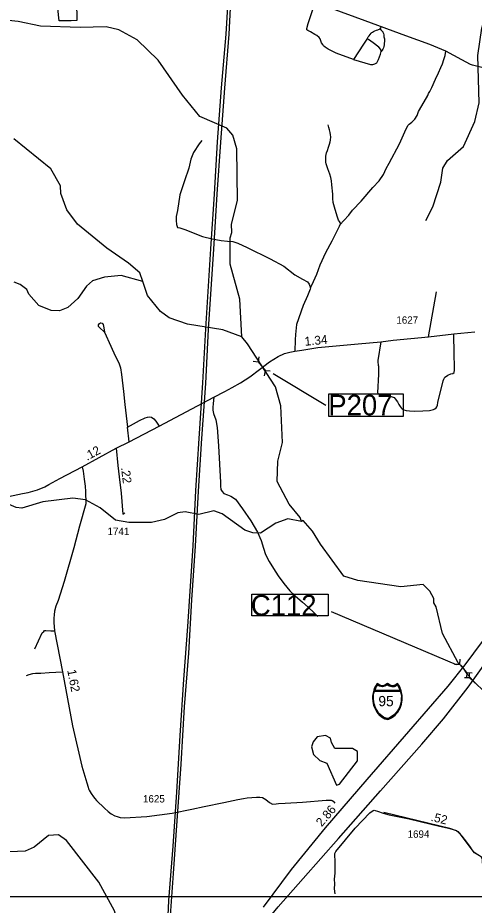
# Model space of a CAD drawing. Extents: x 2290615 to 2522933, y 819489 to 1012715.
# Drawn here: x 2389068 to 2396841, y 958270 to 973391 of the extents above; entities that cross this region are included whole.
import ezdxf

# ---------------------------------------------------------------- set-up
doc = ezdxf.new("R2010")
doc.units = 0
for name, color, linetype in [('Exist Hydrographic Creek Single Shore', 7, 'Continuous'), ('Exist Hydrographic Misc Water Feature', 7, 'Continuous'), ('Exist Hydrographic Pond Under 1500 Sq Ft', 7, 'Continuous'), ('Exist Road Non-System Type 51', 7, 'Continuous'), ('Exist Road Primary Interstate Divided Center Attributed', 7, 'Continuous'), ('Exist Road Primary Interstate Mileage Hundredths English Label', 7, 'Continuous'), ('Exist Road Primary Interstate Shield CELL', 7, 'Continuous'), ('Exist Road Primary Interstate Shield Number Label', 7, 'Continuous'), ('Exist Road Primary Interstate Structure Culvert CELL', 7, 'Continuous'), ('Exist Road Primary Interstate Structure Culvert Number Label', 7, 'Continuous'), ('Exist Road Secondary Mileage Hundredths English Label', 7, 'Continuous'), ('Exist Road Secondary Structure Pipe CELL', 7, 'Continuous'), ('Exist Road Secondary Structure Pipe Number Label', 7, 'Continuous'), ('Exist Road Secondary Type 51 Attributed', 7, 'Continuous'), ('Exist Road Secondary Type 51 Number Label', 7, 'Continuous'), ('Exist Utilities Electrical Transmission Line', 7, 'Continuous'), ('Map Preparation Inset Cut Line', 7, 'Continuous')]:
    doc.layers.add(name, color=color, linetype=linetype)

msp = doc.modelspace()

# ---------------------------------------------------------------- linework, layer by layer
at = {"layer": 'Exist Hydrographic Creek Single Shore'}
for points in [[(2396016, 969935), (2396138, 970170), (2396274, 970589), (2396304, 970830), (2396386, 970958), (2396658, 971196), (2396852, 971621), (2396923, 971939), (2396904, 972749), (2396973, 973215), (2397021, 973381), (2397542, 974289), (2397869, 974736), (2398059, 974894), (2398348, 975074), (2398516, 975142), (2398940, 975254), (2399468, 975422), (2399702, 975418), (2400062, 975289), (2400494, 975362)], [(2391197, 968897), (2390829, 969000), (2390546, 968972), (2390339, 968911), (2390240, 968818), (2390093, 968609), (2389920, 968457), (2389779, 968395), (2389637, 968403), (2389428, 968489), (2389259, 968679), (2389224, 968763), (2389107, 968844), (2389006, 968886)], [(2392885, 967952), (2392558, 968073), (2391957, 968173), (2391647, 968278), (2391496, 968384), (2391275, 968657), (2391197, 968897)], [(2393901, 964809), (2393875, 964874), (2393689, 965106), (2393484, 965488), (2393496, 965837), (2393575, 966155), (2393550, 966778), (2393454, 967102), (2392978, 967837), (2392885, 967952)], [(2397039, 961885), (2396818, 962099), (2396734, 962195), (2396647, 962324), (2396567, 962399), (2396301, 962899), (2396195, 963357), (2396152, 963421), (2396151, 963497), (2396083, 963622), (2395973, 963735), (2395591, 963697), (2394856, 963804), (2394622, 963877), (2394223, 964422), (2394086, 964646), (2393926, 964827), (2393901, 964809)], [(2390741, 958077), (2390738, 958090), (2390714, 958175), (2390450, 958663), (2389898, 959372), (2389764, 959472), (2389589, 959461), (2389350, 959258), (2389193, 959189), (2388935, 959178), (2388609, 959247), (2388315, 959386), (2387641, 959959), (2387514, 960135), (2386992, 961150), (2386714, 961366), (2386572, 961412)]]:
    msp.add_lwpolyline(points, dxfattribs=at)
at = {"layer": 'Exist Hydrographic Misc Water Feature'}
for points in [[(2392885, 967952), (2392851, 968594), (2392685, 969191), (2392687, 969641), (2392711, 969734), (2392709, 969875), (2392812, 970276), (2392800, 971159), (2392731, 971393), (2392629, 971507), (2392168, 971711), (2391872, 972073), (2391456, 972666), (2391101, 973013), (2390791, 973184), (2390573, 973237), (2390132, 973226), (2389457, 973247), (2389072, 973327), (2388805, 973358), (2388645, 973513), (2388377, 973626), (2388325, 973769)], [(2391197, 968897), (2391145, 969046), (2390951, 969212), (2390582, 969466), (2390085, 969875), (2389906, 970121), (2389803, 970396), (2389793, 970530), (2389631, 970819), (2388999, 971328)], [(2393901, 964809), (2393667, 964855), (2393460, 964778), (2393204, 964607), (2393070, 964614), (2392937, 964661), (2392549, 964941), (2392407, 964988), (2392150, 964928), (2391916, 964974), (2391791, 964956), (2391567, 964845), (2391343, 964793), (2390960, 964793), (2390735, 964833), (2390473, 965039), (2390222, 965177), (2390005, 965207), (2389497, 965144), (2389140, 965037), (2389040, 965046), (2388923, 965100), (2388745, 965323), (2388692, 965573)]]:
    msp.add_lwpolyline(points, dxfattribs=at)
at = {"layer": 'Exist Hydrographic Pond Under 1500 Sq Ft'}
msp.add_lwpolyline([(2394544, 960335), (2394855, 960732), (2394853, 960889), (2394769, 960938), (2394469, 960942), (2394409, 961042), (2394391, 961116), (2394308, 961165), (2394166, 961137), (2394101, 961055), (2394069, 960968), (2394103, 960839), (2394213, 960738), (2394331, 960690), (2394494, 960316), (2394544, 960335)], dxfattribs=at)
at = {"layer": 'Exist Road Non-System Type 51'}
for p, q in [((2396062, 967957), (2396198, 968719)), ((2390967, 966166), (2390939, 966417)), ((2390967, 966166), (2390939, 966417))]:
    msp.add_line(p, q, dxfattribs=at)
for points in [[(2390053, 974302), (2390055, 974217), (2390057, 974000), (2390059, 973821), (2390070, 973583), (2390074, 973429), (2390074, 973346), (2389976, 973340), (2389804, 973338), (2389775, 973340), (2389765, 973390), (2389755, 973496), (2389748, 973641), (2389734, 973863), (2389724, 974025), (2389724, 974118), (2389726, 974168)], [(2394786, 972682), (2394490, 972790), (2394352, 972856), (2394302, 972887), (2394277, 972912), (2394261, 972934), (2394240, 972964), (2394228, 972997), (2394215, 973032), (2394198, 973057), (2394161, 973087), (2394124, 973108), (2394055, 973149), (2394007, 973171), (2393991, 973185), (2393993, 973210), (2394013, 973292), (2394056, 973430), (2394133, 973646)], [(2395017, 973034), (2395027, 973056), (2395035, 973068), (2395049, 973084), (2395069, 973107), (2395087, 973128), (2395100, 973139), (2395111, 973147), (2395126, 973157), (2395149, 973167), (2395175, 973178), (2395199, 973187), (2395213, 973191), (2395227, 973197), (2395239, 973200)], [(2395239, 973200), (2395250, 973218), (2395259, 973236)], [(2395239, 973200), (2395253, 973184), (2395269, 973166), (2395280, 973156), (2395285, 973149), (2395287, 973143), (2395290, 973133), (2395295, 973121), (2395299, 973101), (2395302, 973082), (2395304, 973068), (2395309, 973049), (2395312, 973032), (2395311, 973008), (2395311, 972984), (2395308, 972959), (2395305, 972929), (2395302, 972903), (2395296, 972881), (2395286, 972857), (2395276, 972837), (2395258, 972818)], [(2395017, 973034), (2395014, 973028), (2395001, 973011), (2394958, 972943), (2394786, 972682)], [(2395258, 972818), (2395248, 972849), (2395214, 972891), (2395118, 972965), (2395041, 973019), (2395029, 973028), (2395017, 973034)], [(2394558, 969866), (2394620, 969934), (2394706, 970026), (2394770, 970111), (2394914, 970266), (2395117, 970498), (2395223, 970612), (2395294, 970723), (2395344, 970823), (2395394, 970915), (2395566, 971243), (2395684, 971498), (2395718, 971558), (2395735, 971575), (2395776, 971611), (2395828, 971665), (2395868, 971728), (2395893, 971792), (2395947, 971893), (2396050, 972064), (2396064, 972101), (2396083, 972133), (2396119, 972204), (2396183, 972344), (2396231, 972454), (2396273, 972542), (2396298, 972605), (2396323, 972680), (2396344, 972747), (2396359, 972819)], [(2394786, 972682), (2395072, 972597), (2395113, 972597), (2395150, 972608), (2395185, 972624), (2395213, 972678), (2395244, 972770), (2395258, 972818)], [(2394558, 969866), (2394561, 969877), (2394561, 969887), (2394556, 969902), (2394547, 969919), (2394532, 969945), (2394505, 970008), (2394460, 970163), (2394441, 970245), (2394431, 970310), (2394431, 970387), (2394418, 970542), (2394409, 970612), (2394399, 970670), (2394382, 970728), (2394349, 970816), (2394330, 970866), (2394321, 970903), (2394316, 970929), (2394313, 970983), (2394316, 971034), (2394327, 971090), (2394341, 971132), (2394357, 971185), (2394376, 971236), (2394389, 971276), (2394393, 971303), (2394399, 971361), (2394394, 971394), (2394389, 971438), (2394378, 971481), (2394367, 971519), (2394356, 971567)], [(2392202, 971302), (2392157, 971240), (2392062, 971095), (2392016, 970981), (2391980, 970828), (2391908, 970615), (2391830, 970374), (2391788, 970109), (2391767, 970005), (2391766, 969937), (2391773, 969869), (2391788, 969820), (2391827, 969812), (2391915, 969783), (2392214, 969662), (2392376, 969622), (2392531, 969595), (2392638, 969587), (2392731, 969577), (2392813, 969551), (2392974, 969479), (2393368, 969286), (2393600, 969159), (2393785, 969010), (2393917, 968937), (2394000, 968889), (2394031, 968852), (2394050, 968791)], [(2394050, 968791), (2394106, 968895), (2394160, 969021), (2394220, 969182), (2394316, 969389), (2394419, 969589), (2394496, 969739), (2394548, 969840), (2394558, 969866)], [(2394050, 968791), (2394047, 968769), (2394004, 968651), (2393930, 968489), (2393813, 968162), (2393796, 967996), (2393792, 967906), (2393786, 967713)], [(2390543, 968032), (2390458, 968111), (2390445, 968133), (2390443, 968157), (2390459, 968179), (2390474, 968191), (2390480, 968191), (2390507, 968186), (2390523, 968162), (2390534, 968106), (2390543, 968032)], [(2390543, 968032), (2390458, 968111), (2390445, 968133), (2390443, 968157), (2390459, 968179), (2390474, 968191), (2390480, 968191), (2390507, 968186), (2390523, 968162), (2390534, 968106), (2390543, 968032)], [(2390543, 968032), (2390655, 967798), (2390726, 967630), (2390772, 967548), (2390795, 967493), (2390815, 967425), (2390835, 967310), (2390868, 967023), (2390890, 966804), (2390939, 966417)], [(2395249, 967871), (2395201, 967550), (2395200, 967516), (2395204, 967482), (2395206, 967474), (2395210, 967453), (2395213, 967441), (2395213, 967424), (2395213, 967407), (2395210, 967317), (2395194, 967001), (2395229, 966973), (2395272, 966964), (2395327, 966956), (2395388, 966948), (2395441, 966933), (2395475, 966919), (2395495, 966899), (2395532, 966847), (2395558, 966799), (2395577, 966768), (2395597, 966746), (2395615, 966726), (2395643, 966710), (2395684, 966702), (2395739, 966695), (2395820, 966689), (2395967, 966691), (2396078, 966699), (2396149, 966716), (2396172, 966727), (2396190, 966744), (2396205, 966764), (2396213, 966788), (2396222, 966836), (2396310, 967205), (2396323, 967233), (2396341, 967266), (2396366, 967286), (2396390, 967302), (2396443, 967322), (2396478, 967330), (2396502, 967348), (2396503, 967384), (2396507, 967441), (2396499, 967662), (2396493, 968008)], [(2392404, 966924), (2392397, 966819), (2392388, 966749), (2392387, 966707), (2392401, 966648), (2392441, 966540), (2392465, 966412), (2392485, 966095), (2392523, 965473), (2392522, 965413), (2392525, 965355), (2392547, 965318), (2392575, 965288), (2392640, 965261), (2392698, 965238), (2392773, 965187), (2392895, 965022), (2393036, 964818), (2393152, 964626), (2393214, 964483), (2393252, 964355), (2393285, 964248), (2393347, 964124), (2393422, 964009), (2393504, 963880), (2393596, 963752), (2393703, 963627), (2393791, 963542), (2393918, 963432), (2394013, 963347), (2394116, 963253), (2394177, 963188)], [(2392404, 966924), (2392397, 966819), (2392388, 966749), (2392387, 966707), (2392401, 966648), (2392441, 966540), (2392465, 966412), (2392485, 966095), (2392523, 965473), (2392522, 965413), (2392525, 965355), (2392547, 965318), (2392575, 965288), (2392640, 965261), (2392698, 965238), (2392773, 965187), (2392895, 965022), (2393036, 964818), (2393152, 964626), (2393214, 964483), (2393252, 964355), (2393285, 964248), (2393347, 964124), (2393422, 964009), (2393504, 963880), (2393596, 963752), (2393703, 963627), (2393791, 963542), (2393918, 963432), (2394013, 963347), (2394116, 963253), (2394177, 963188)], [(2390939, 966417), (2391139, 966529), (2391235, 966572), (2391279, 966587), (2391311, 966593), (2391348, 966583), (2391383, 966560), (2391421, 966517), (2391476, 966435)], [(2390939, 966417), (2391139, 966529), (2391235, 966572), (2391279, 966587), (2391311, 966593), (2391348, 966583), (2391383, 966560), (2391421, 966517), (2391476, 966435)], [(2389361, 962636), (2389486, 962910), (2389509, 962934), (2389522, 962949), (2389548, 962954), (2389629, 962946), (2389693, 962947)], [(2389361, 962636), (2389486, 962910), (2389509, 962934), (2389522, 962949), (2389548, 962954), (2389629, 962946), (2389693, 962947)], [(2389218, 962184), (2389262, 962199), (2389325, 962221), (2389369, 962226), (2389462, 962226), (2389603, 962233), (2389830, 962246)], [(2392973, 960100), (2393132, 960110), (2393192, 960113), (2393236, 960104), (2393295, 960073), (2393352, 960023), (2393406, 959991), (2393469, 959997), (2393510, 960001), (2393622, 960007), (2393919, 960029), (2394320, 960060), (2394404, 960062), (2394420, 960056), (2394436, 960044), (2394465, 960011), (2394466, 960008)], [(2394472, 958462), (2394459, 958549), (2394466, 958636), (2394462, 958712), (2394472, 958816), (2394472, 958934), (2394474, 959038), (2394468, 959109), (2394466, 959129), (2394467, 959154), (2394482, 959186), (2394813, 959583), (2395063, 959842), (2395118, 959887), (2395137, 959889), (2395156, 959884), (2395195, 959873), (2395288, 959841), (2395392, 959813), (2395564, 959777), (2395732, 959742), (2395923, 959696), (2396248, 959619), (2396401, 959581), (2396485, 959561), (2396524, 959547), (2396559, 959528), (2396587, 959500), (2396628, 959445), (2396669, 959397), (2396728, 959325), (2396758, 959274), (2396802, 959214), (2396840, 959173), (2396904, 959136)]]:
    msp.add_lwpolyline(points, dxfattribs=at)
at = {"layer": 'Exist Road Primary Interstate Divided Center Attributed'}
for points in [[(2399046, 967475), (2398943, 967142), (2398738, 966520), (2398600, 966108), (2398412, 965558), (2398229, 965078), (2398095, 964755), (2397910, 964355), (2397639, 963833), (2397458, 963516), (2397157, 963036), (2396977, 962766), (2396683, 962367), (2396390, 962003), (2395721, 961232), (2395013, 960413), (2394302, 959589), (2393726, 958881), (2393244, 958235)], [(2391225, 954740), (2391718, 955662), (2392098, 956322), (2392304, 956642), (2392559, 957026), (2392813, 957379), (2393142, 957807), (2393503, 958245), (2393930, 958726), (2394529, 959405), (2395244, 960218), (2395946, 961013), (2396320, 961447), (2396738, 961985), (2396963, 962303), (2397189, 962656), (2397408, 963015), (2397617, 963399), (2397800, 963761), (2397944, 964074), (2398121, 964482), (2398330, 965052), (2398514, 965606), (2398551, 965715)]]:
    msp.add_lwpolyline(points, dxfattribs=at)
at = {"layer": 'Exist Road Primary Interstate Shield CELL'}
for points in [[(2395362, 961437), (2395372, 961438), (2395385, 961441), (2395397, 961445), (2395411, 961451), (2395432, 961463), (2395449, 961472), (2395468, 961485), (2395494, 961509), (2395520, 961537), (2395543, 961568), (2395561, 961597), (2395577, 961630), (2395591, 961661), (2395602, 961696), (2395609, 961730), (2395612, 961766), (2395615, 961806), (2395612, 961850), (2395604, 961896), (2395597, 961924), (2395586, 961958), (2395577, 961980), (2395556, 962018), (2395537, 962048), (2395510, 962029), (2395492, 962019), (2395481, 962014), (2395470, 962012), (2395450, 962010), (2395437, 962010), (2395425, 962013), (2395415, 962015), (2395407, 962019), (2395362, 962048), (2395318, 962019), (2395309, 962015), (2395299, 962013), (2395290, 962010), (2395275, 962010), (2395263, 962010), (2395252, 962012), (2395242, 962014), (2395232, 962019), (2395187, 962048), (2395169, 962022), (2395154, 961997), (2395139, 961961), (2395129, 961933), (2395123, 961910), (2395114, 961868), (2395110, 961831), (2395109, 961806), (2395114, 961741), (2395121, 961707), (2395128, 961679), (2395152, 961619), (2395170, 961585), (2395185, 961561), (2395207, 961534), (2395219, 961521), (2395264, 961482), (2395293, 961461), (2395317, 961448), (2395329, 961444), (2395346, 961439)], [(2395192, 962027), (2395181, 962010), (2395168, 961987), (2395158, 961963), (2395148, 961937), (2395579, 961937), (2395569, 961960), (2395559, 961982), (2395547, 962003), (2395534, 962023), (2395509, 962007), (2395492, 961999), (2395478, 961994), (2395466, 961991), (2395447, 961990), (2395439, 961990), (2395413, 961996), (2395395, 962003), (2395378, 962015), (2395365, 962027), (2395331, 962007), (2395316, 962000), (2395298, 961996), (2395279, 961993), (2395250, 961996), (2395227, 962004), (2395207, 962015)], [(2395582, 961916), (2395587, 961904), (2395593, 961877), (2395596, 961856), (2395600, 961832), (2395598, 961791), (2395596, 961748), (2395593, 961723), (2395587, 961700), (2395580, 961674), (2395569, 961641), (2395553, 961612), (2395533, 961580), (2395511, 961552), (2395502, 961541), (2395484, 961522), (2395452, 961496), (2395429, 961479), (2395400, 961462), (2395386, 961456), (2395369, 961452), (2395356, 961453), (2395339, 961458), (2395326, 961461), (2395296, 961477), (2395272, 961493), (2395233, 961526), (2395211, 961551), (2395191, 961580), (2395173, 961610), (2395154, 961650), (2395141, 961690), (2395131, 961733), (2395124, 961786), (2395124, 961818), (2395126, 961848), (2395128, 961865), (2395132, 961885), (2395140, 961916)]]:
    msp.add_lwpolyline(points, close=True, dxfattribs=at)
at = {"layer": 'Exist Road Primary Interstate Structure Culvert CELL'}
for p, q in [((2396596, 962460), (2396589, 962377)), ((2396506, 962379), (2396589, 962377)), ((2396589, 962377), (2396721, 962229)), ((2396673, 962148), (2396757, 962152)), ((2396714, 962146), (2396721, 962229)), ((2396804, 962226), (2396721, 962229)), ((2396757, 962235), (2396757, 962152)), ((2396900, 962014), (2396757, 962152))]:
    msp.add_line(p, q, dxfattribs=at)
at = {"layer": 'Exist Road Primary Interstate Structure Culvert Number Label'}
msp.add_line((2396537, 962366), (2394408, 963267), dxfattribs=at)
msp.add_lwpolyline([(2393054, 963569), (2394351, 963569), (2394351, 963200), (2393054, 963200)], close=True, dxfattribs=at)
at = {"layer": 'Exist Road Secondary Structure Pipe CELL'}
for p, q in [((2393175, 967613), (2393162, 967531)), ((2393079, 967539), (2393162, 967531)), ((2393162, 967531), (2393284, 967375)), ((2393272, 967292), (2393284, 967375)), ((2393367, 967367), (2393284, 967375))]:
    msp.add_line(p, q, dxfattribs=at)
at = {"layer": 'Exist Road Secondary Structure Pipe Number Label'}
msp.add_line((2393415, 967327), (2394316, 966789), dxfattribs=at)
msp.add_lwpolyline([(2394363, 966981), (2395629, 966981), (2395629, 966598), (2394363, 966598)], close=True, dxfattribs=at)
at = {"layer": 'Exist Road Secondary Type 51 Attributed'}
msp.add_line((2390167, 965741), (2390744, 966055), dxfattribs=at)
for points in [[(2398125, 972339), (2397785, 972397), (2397373, 972471), (2396970, 972545), (2396811, 972582), (2396777, 972595), (2396631, 972672), (2396359, 972819), (2396085, 972935), (2395679, 973084), (2394982, 973336), (2394411, 973548)], [(2390744, 966055), (2390967, 966166), (2391476, 966435), (2392404, 966924), (2392593, 967022), (2392720, 967094), (2392862, 967172), (2393021, 967274), (2393185, 967400), (2393354, 967530), (2393500, 967618), (2393612, 967668), (2393701, 967696), (2393786, 967713), (2393905, 967727), (2394176, 967771), (2394863, 967836), (2395249, 967871), (2395460, 967900), (2396062, 967957), (2396493, 968008), (2396852, 968039)], [(2390744, 966055), (2390771, 965765), (2390795, 965568), (2390830, 965289), (2390858, 964936), (2390889, 964958)], [(2387348, 964505), (2387858, 964763), (2388236, 964958), (2388453, 965070), (2388638, 965160), (2388757, 965197), (2388829, 965216), (2388987, 965250), (2389147, 965283), (2389245, 965303), (2389405, 965346), (2389527, 965398), (2389596, 965436), (2389785, 965543), (2390167, 965741)], [(2390167, 965741), (2390183, 965667), (2390196, 965528), (2390215, 965413), (2390224, 965321), (2390229, 965109), (2390122, 964729), (2390022, 964359), (2389856, 963786), (2389754, 963464), (2389717, 963368), (2389694, 963279), (2389686, 963218), (2389684, 963160), (2389682, 963090), (2389693, 962947), (2389830, 962246), (2389856, 962096), (2390002, 961328), (2390159, 960640), (2390245, 960355), (2390267, 960280), (2390275, 960255), (2390286, 960231), (2390316, 960176), (2390355, 960120), (2390379, 960091), (2390409, 960053), (2390545, 959923), (2390605, 959868), (2390659, 959826), (2390723, 959794), (2390763, 959780), (2390812, 959764), (2390884, 959757), (2391264, 959783), (2391695, 959837), (2392031, 959905), (2392240, 959951), (2392575, 960020), (2392814, 960069), (2392912, 960091), (2392973, 960100)], [(2397521, 958632), (2397284, 958641), (2397194, 958675), (2397111, 958729), (2397045, 958785), (2397001, 958840), (2396982, 959017), (2396979, 959050), (2396963, 959087), (2396932, 959111), (2396845, 959163), (2396599, 959489), (2396538, 959536), (2396426, 959578), (2395299, 959849)]]:
    msp.add_lwpolyline(points, dxfattribs=at)
at = {"layer": 'Exist Utilities Electrical Transmission Line'}
for points in [[(2392683, 974342), (2392610, 973112), (2392534, 972195), (2392466, 971278), (2392410, 970387), (2392348, 969455), (2392264, 968092), (2392215, 967169), (2392153, 966224), (2392097, 965336), (2392047, 964395), (2391960, 963020), (2391892, 962115), (2391826, 961163), (2391769, 960194), (2391706, 959275), (2391636, 958352), (2391625, 958096)], [(2391667, 958097), (2391722, 958809), (2391782, 959710), (2391851, 960671), (2391906, 961652), (2391980, 962566), (2392034, 963471), (2392092, 964386), (2392147, 965326), (2392203, 966225), (2392269, 967160), (2392318, 968086), (2392406, 969449), (2392464, 970384), (2392528, 971269), (2392596, 972189), (2392666, 973110), (2392731, 974335)]]:
    msp.add_lwpolyline(points, dxfattribs=at)
at = {"layer": 'Map Preparation Inset Cut Line'}
msp.add_lwpolyline([(2369932, 996959), (2400126, 996959), (2403338, 985770), (2415972, 978275), (2416026, 958414), (2369771, 958414)], close=True, dxfattribs=at)

# ---------------------------------------------------------------- texts
at = {"layer": 'Exist Road Primary Interstate Mileage Hundredths English Label'}
msp.add_text('2.86', height=150, rotation=49.1645, dxfattribs=at).set_placement((2394244, 959599))
at = {"layer": 'Exist Road Primary Interstate Shield Number Label'}
msp.add_text('95', height=175, dxfattribs=at).set_placement((2395209, 961661))
at = {"layer": 'Exist Road Primary Interstate Structure Culvert Number Label'}
msp.add_text('C112', height=350, dxfattribs=at).set_placement((2393037, 963206))
at = {"layer": 'Exist Road Secondary Mileage Hundredths English Label'}
for s, rotation, p in [('1.34', 5.4111, (2393959, 967801)), ('.12', 28.5531, (2390248, 965842)), ('.22', 277.3404, (2390825, 965725)), ('1.62', 280.7017, (2389910, 962274)), ('.52', 346.5029, (2396093, 959709))]:
    msp.add_text(s, height=150, rotation=rotation, dxfattribs=at).set_placement(p)
at = {"layer": 'Exist Road Secondary Structure Pipe Number Label'}
msp.add_text('P207', height=350, rotation=360, dxfattribs=at).set_placement((2394356, 966617))
at = {"layer": 'Exist Road Secondary Type 51 Number Label'}
for s, p in [('1627', (2395515, 968178)), ('1741', (2390596, 964578))]:
    msp.add_text(s, height=125, dxfattribs=at).set_placement(p)
for s, p in [('1625', (2391200, 960021)), ('1694', (2395706, 959420))]:
    msp.add_text(s, height=125, rotation=360, dxfattribs=at).set_placement(p)

doc.saveas('drawing.dxf')
